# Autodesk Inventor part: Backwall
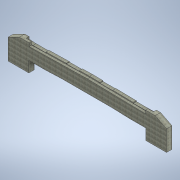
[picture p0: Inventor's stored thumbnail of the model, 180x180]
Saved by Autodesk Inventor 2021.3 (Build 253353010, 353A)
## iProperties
Created: 2021-11
Part Number: Backwall
Material: Concrete, Cast-in-Place, Gray
Document SubType Name: Modeling
Designer: u1426
Density: 2.40731 g/cm^3
Appearance: Flat - Gray 1
Author: u1426
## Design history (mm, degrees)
sketch "Sketch1"
  geometry: L1 (-5505.45, 0)-(-5505.45, 1016); L2 (5505.45, 0)-(5505.45, 1016); L3 (5505.45, 1016)-(3962.4, 1016); L4 (-5505.45, 1016)-(-3962.4, 1016); L5 (-3962.4, 1016)-(-2336.8, 1076.96); L6 (-2336.8, 1076.96)-(2336.8, 1076.96); L7 (2336.8, 1076.96)-(3962.4, 1016); L8 (-5505.45, 0)-(-7467.6, 0); L9 (-7467.6, 0)-(-7467.6, 1943.1); L10 (5505.45, 0)-(7467.6, 0); L11 (7467.6, 0)-(7467.6, 1936.75); L12 (6400.8, 2470.15)-(5486.4, 2470.15); L13 (5486.4, 2470.15)-(0, 2586.228); L14 (-6400.8, 2476.5)-(-5486.4, 2476.5); L15 (-5486.4, 2476.5)-(0, 2586.228); L16 (-6400.8, 2476.5)-(-7467.6, 1943.1); L17 (6400.8, 2470.15)-(7467.6, 1936.75); 3 further points
  constraints: 34 end point, 5 horizontal, 4 perpendicular, 4 point on line, 2 vertical, 1 collinear
  dimensions: "d0" = 5505.45 distance of point (0, 0) L1.start; "d4" = 1543.05 distance of L2.end L3.end; "d5" = 1543.05 distance of L1.end L4.end; "d6" = 1625.6 horizontal distance of L6.end L3.end; "d7" = 1625.6 horizontal distance of L4.end L5.end; "d8" = 4673.6 distance of L5.end L6.end (derived); "d9" = 2336.8 horizontal distance of L5.end point (0, 0) (derived); "d10" = 60.96 vertical distance of L4.end L5.end; "d30" = 5505.45 distance from line of point (0, 0) L2; "d31" = 1016 distance of L1.start L1.end; "d32" = 1016 distance of L2.start L2.end; "d33" = 1962.15 distance of L1.start L8.end; "d34" = 2476.5 distance of L8.end point (-7467.6, 2476.5); "d35" = 1962.15 distance of L2.start L10.end; "d36" = 2470.15 distance of L10.end point (7467.6, 2470.15); "d37" = 1981.2 distance of point (7467.6, 2470.15) L12.end; "d38" = 1981.2 distance of point (-7467.6, 2476.5) L14.end; "d39" = 5486.4 horizontal distance of L14.end L13.end; "d41" = 5486.4 horizontal distance of L12.end L13.end; "d42" = 109.728 vertical distance of L14.end L13.end; "d43" = 1066.8 distance of L14.start point (-7467.6, 2476.5); "d44" = 533.4 distance of L9.end point (-7467.6, 2476.5); "d45" = 1066.8 distance of L12.start point (7467.6, 2470.15) (= d43); "d46" = 533.4 distance of L11.end point (7467.6, 2470.15) (= d44)
extrude "Extrusion1" new body sketch "Sketch1" distance "d11" = 508; taper "d12" = 0 deg
sketch "Sketch3"
  geometry: L1 (0, 2586.228)-(-5486.4, 2476.5) reference; L2 (5486.4, 2470.15)-(0, 2586.228) reference; L3 (-5486.4, 2476.5)-(0, 2586.228) reference; L4 (-5486.4, 2476.5)-(-5486.4, 2171.7); L5 (5486.4, 2470.15)-(5486.4, 2165.35); L6 (5486.4, 2165.35)-(0, 2281.428); L7 (0, 2281.428)-(-5486.4, 2171.7); 1 further point
  constraints: 8 end point, 2 parallel, 2 vertical
  dimensions: "d47" = 304.8 distance of L1.end L4.end; "d48" = 304.8 distance of L2.start L5.end
extrude "Extrusion2" cut sketch "Sketch3" distance "d49" = 228.6; taper "d50" = 0 deg
sketch "Sketch4"
  geometry: L1 (-5505.45, 1016)-(-3962.4, 1016) reference; L2 (-3962.4, 1016)-(-2336.8, 1076.96) reference; L3 (-2336.8, 1076.96)-(2336.8, 1076.96) reference; L4 (2336.8, 1076.96)-(3962.4, 1016) reference; L5 (3962.4, 1016)-(5505.45, 1016) reference; L6 (5486.4, 1022.35)-(3962.519, 1022.35); L7 (3962.519, 1022.35)-(2336.919, 1083.31); L8 (2336.919, 1083.31)-(-2336.919, 1083.31); L9 (-2336.919, 1083.31)-(-3962.519, 1022.35); L10 (-3962.519, 1022.35)-(-5486.4, 1022.35); L11 (-5505.45, 0)-(-5505.45, 1016) reference; L12 (5486.4, 1016)-(5486.4, 1022.35); L13 (5505.45, 1016)-(5505.45, 0) reference; L14 (-3962.4, 1016)-(-5505.45, 1016) reference; L15 (-5486.4, 1016)-(-5486.4, 1022.35); 2 further points
  constraints: 14 end point, 2 perpendicular, 2 point on line, 2 other
  dimensions: "d51" = 6.35 distance between parallel lines of L3 L8; "d52" = 19.05 distance between parallel lines of L12 L13; "d53" = 19.05 distance between parallel lines of L15 L11
extrude "Extrusion3" cut sketch "Sketch4" distance "d54" = 76.2; taper "d55" = 0 deg
sketch "Sketch5"
  geometry: L1 (-5505.45, 1016)-(-3962.4, 1016) reference; L2 (-3962.4, 1016)-(-2336.8, 1076.96) reference; L3 (-2336.8, 1076.96)-(2336.8, 1076.96) reference; L4 (2336.8, 1076.96)-(3962.4, 1016) reference; L5 (3962.4, 1016)-(5505.45, 1016) reference; L6 (5486.4, 1022.35)-(3962.519, 1022.35); L7 (3962.519, 1022.35)-(2336.919, 1083.31); L8 (2336.919, 1083.31)-(-2336.919, 1083.31); L9 (-2336.919, 1083.31)-(-3962.519, 1022.35); L10 (-3962.519, 1022.35)-(-5486.4, 1022.35); L11 (-5486.4, 1022.35)-(-5486.4, 1016) reference; L12 (5486.4, 1016)-(5486.4, 1022.35) reference; 1 further point
  constraints: 10 end point, 2 point on line, 2 other
  dimensions: "d56" = 6.35 distance between parallel lines of L3 L8
extrude "Extrusion4" cut sketch "Sketch5" distance "d57" = 76.2; taper "d58" = 0 deg
sketch "Sketch6"
  geometry: L1 (0, 2586.228)-(-5486.4, 2470.15) reference; L2 (5486.4, 2476.5)-(0, 2586.228) reference; L3 (-5486.4, 2470.15)-(-5994.4, 2470.15); L4 (-5486.4, 2470.15)-(-6400.8, 2470.15) reference; L5 (-5994.4, 2470.15)-(-5994.4, 2266.95); L6 (5486.4, 2476.5)-(5994.4, 2476.5); L7 (5486.4, 2476.5)-(6400.8, 2476.5) reference; L8 (5994.4, 2476.5)-(5994.4, 2273.3); L9 (-5994.4, 2266.95)-(-5334, 2213.024); L10 (-5334, 2213.024)-(-5334, 2225.724); L11 (-5334, 2225.724)-(-4114.8, 2225.724); L12 (-4114.8, 2225.724)-(-4114.8, 2289.573); L13 (-4114.8, 2289.573)-(-2184.4, 2330.415); L14 (-2184.4, 2330.415)-(-2184.4, 2292.362); L15 (-2184.4, 2292.362)-(-965.2, 2292.362); L16 (-965.2, 2292.362)-(-965.2, 2356.21); L17 (-965.2, 2356.21)-(0.121, 2376.634); L18 (0.121, 2376.634)-(965.2, 2357.332); L19 (965.2, 2357.332)-(965.2, 2294.89); L20 (965.2, 2294.89)-(2184.4, 2294.89); L21 (2184.4, 2294.89)-(2184.4, 2332.948); L22 (2184.4, 2332.948)-(4114.8, 2294.34); L23 (4114.8, 2294.34)-(4114.8, 2231.898); L24 (4114.8, 2231.898)-(5334, 2231.898); L25 (5334, 2231.898)-(5334, 2219.198); L26 (5334, 2219.198)-(5994.4, 2273.3); L27 (-2184.4, 2292.362)-(-2184.4, 2540.012); L28 (2184.4, 2294.89)-(2184.4, 2542.54); L29 (5486.4, 2476.5)-(0, 2586.228) reference; L30 (5334, 2231.898)-(5334, 2479.548); L31 (-5334, 2225.724)-(-5334, 2473.374); 1 further point
  constraints: 52 end point, 8 vertical, 7 parallel, 7 perpendicular, 6 point on line
  dimensions: "d59" = 508 distance of L1.end L3.end; "d60" = 203.2 distance of L3.end L5.end; "d61" = 508 distance of L2.start L6.end; "d63" = 203.2 distance of L6.end L8.end; "d64" = 12.7 distance of L9.end L10.end; "d65" = 1219.2 distance of L10.end L11.end; "d66" = 1219.2 distance of L14.end L15.end; "d67" = 1219.2 distance of L19.end L20.end; "d68" = 1219.2 distance of L23.end L24.end; "d69" = 12.7 distance of L24.end L25.end; "d70" = 209.55 distance between parallel lines of L18 L2; "d71" = 209.55 distance between parallel lines of L17 L1; "d72" = 209.55 distance between parallel lines of L13 L1; "d73" = 209.55 distance between parallel lines of L22 L2; "d77" = 247.65 distance of L14.end L27.end; "d78" = 247.65 distance of L20.end L28.end; "d79" = 247.65 distance of L10.end L31.end; "d81" = 247.65 distance of L24.end L30.end; "d84" = 1930.4 distance between parallel lines of L14 L12; "d85" = 965.2 distance from line of L1.start L16; "d86" = 965.2 distance from line of L1.start L19; "d87" = 1930.4 distance between parallel lines of L23 L21
extrude "Extrusion5" cut sketch "Sketch6" distance "d82" = 279.4; taper "d83" = 0 deg
body "Solid1"
